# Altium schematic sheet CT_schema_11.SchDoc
size 274 x 160 mm
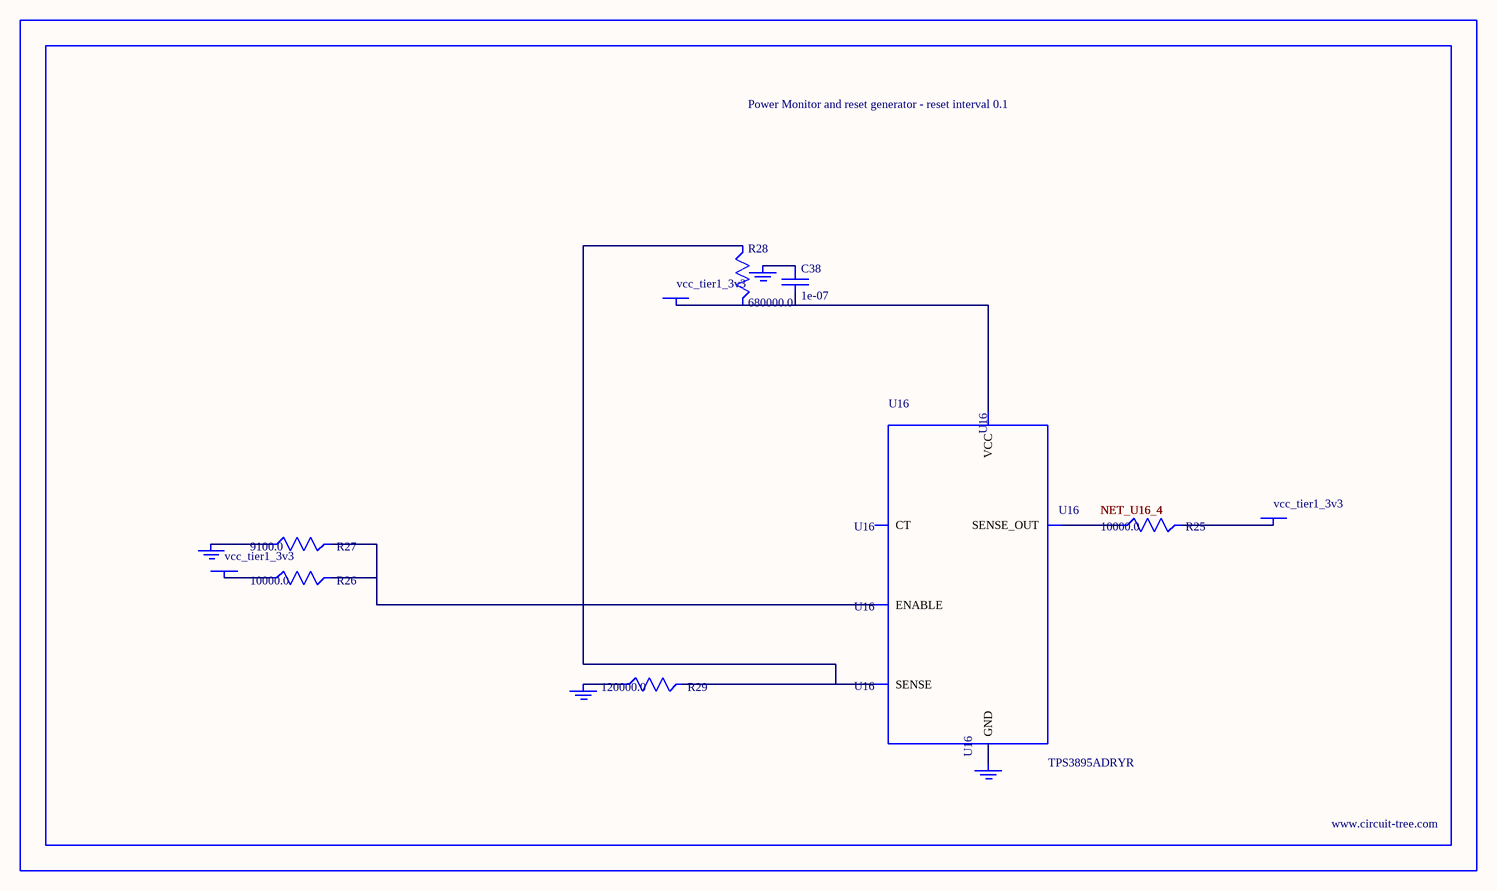
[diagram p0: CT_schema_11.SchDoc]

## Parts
BORDER10  (no value)
C38  1e-07  [C0402]
GND_INSTANCE_10_0  (no value)
GND_INSTANCE_10_1  (no value)
GND_INSTANCE_10_2  (no value)
GND_INSTANCE_10_3  (no value)
POWER_INSTANCE_10_0  vcc_tier1_3v3
POWER_INSTANCE_10_1  vcc_tier1_3v3
POWER_INSTANCE_10_2  vcc_tier1_3v3
R25  10000.0  [R0603]
R26  10000.0  [R0603]
R27  9100.0  [R0603]
R28  680000.0  [R0603]
R29  120000.0  [R0603]
U16  TPS3895ADRYR  [SON-6]

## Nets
NetC38_1: C38.1 GND_INSTANCE_10_2.0(GND)
NetC38_2: C38.2 POWER_INSTANCE_10_2.0(PWR) R28.2 U16.6(VCC)
NetGND_INSTANCE_10_0_0: GND_INSTANCE_10_0.0(GND) R27.1
NetGND_INSTANCE_10_1_0: GND_INSTANCE_10_1.0(GND) R29.1
NetGND_INSTANCE_10_3_0: GND_INSTANCE_10_3.0(GND) U16.2(GND)
NetPOWER_INSTANCE_10_0_0: POWER_INSTANCE_10_0.0(PWR) R26.1
NetPOWER_INSTANCE_10_1_0: POWER_INSTANCE_10_1.0(PWR) R25.2
NetR25_1: R25.1 U16.4(SENSE_OUT)
NetR26_2: R26.2 R27.2 U16.1(ENABLE)
NetR28_1: R28.1 R29.2 U16.3(SENSE)

Not connected (* = marked no-connect by the designer): U16 5(CT)

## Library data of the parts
BORDER10 = BORDER_PAGE10
C38 = C0402C104K3RACTU
GND_INSTANCE_10_0-GND_INSTANCE_10_3 = GND
POWER_INSTANCE_10_0-POWER_INSTANCE_10_2 = PWR
R25 R26 = RC0603JR-0710KL
R27 = RC0603JR-079K1L
R28 = RC0603JR-07680KL
R29 = RC0603JR-07120KL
